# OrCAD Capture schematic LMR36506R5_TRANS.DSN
size D; title: LMR36506R5, 3 V 65 V, 0.6-A Ultra-Small Synchronous; rev: 1.0; note: Datasheet: SNVSBB6        EVM: SNVU671
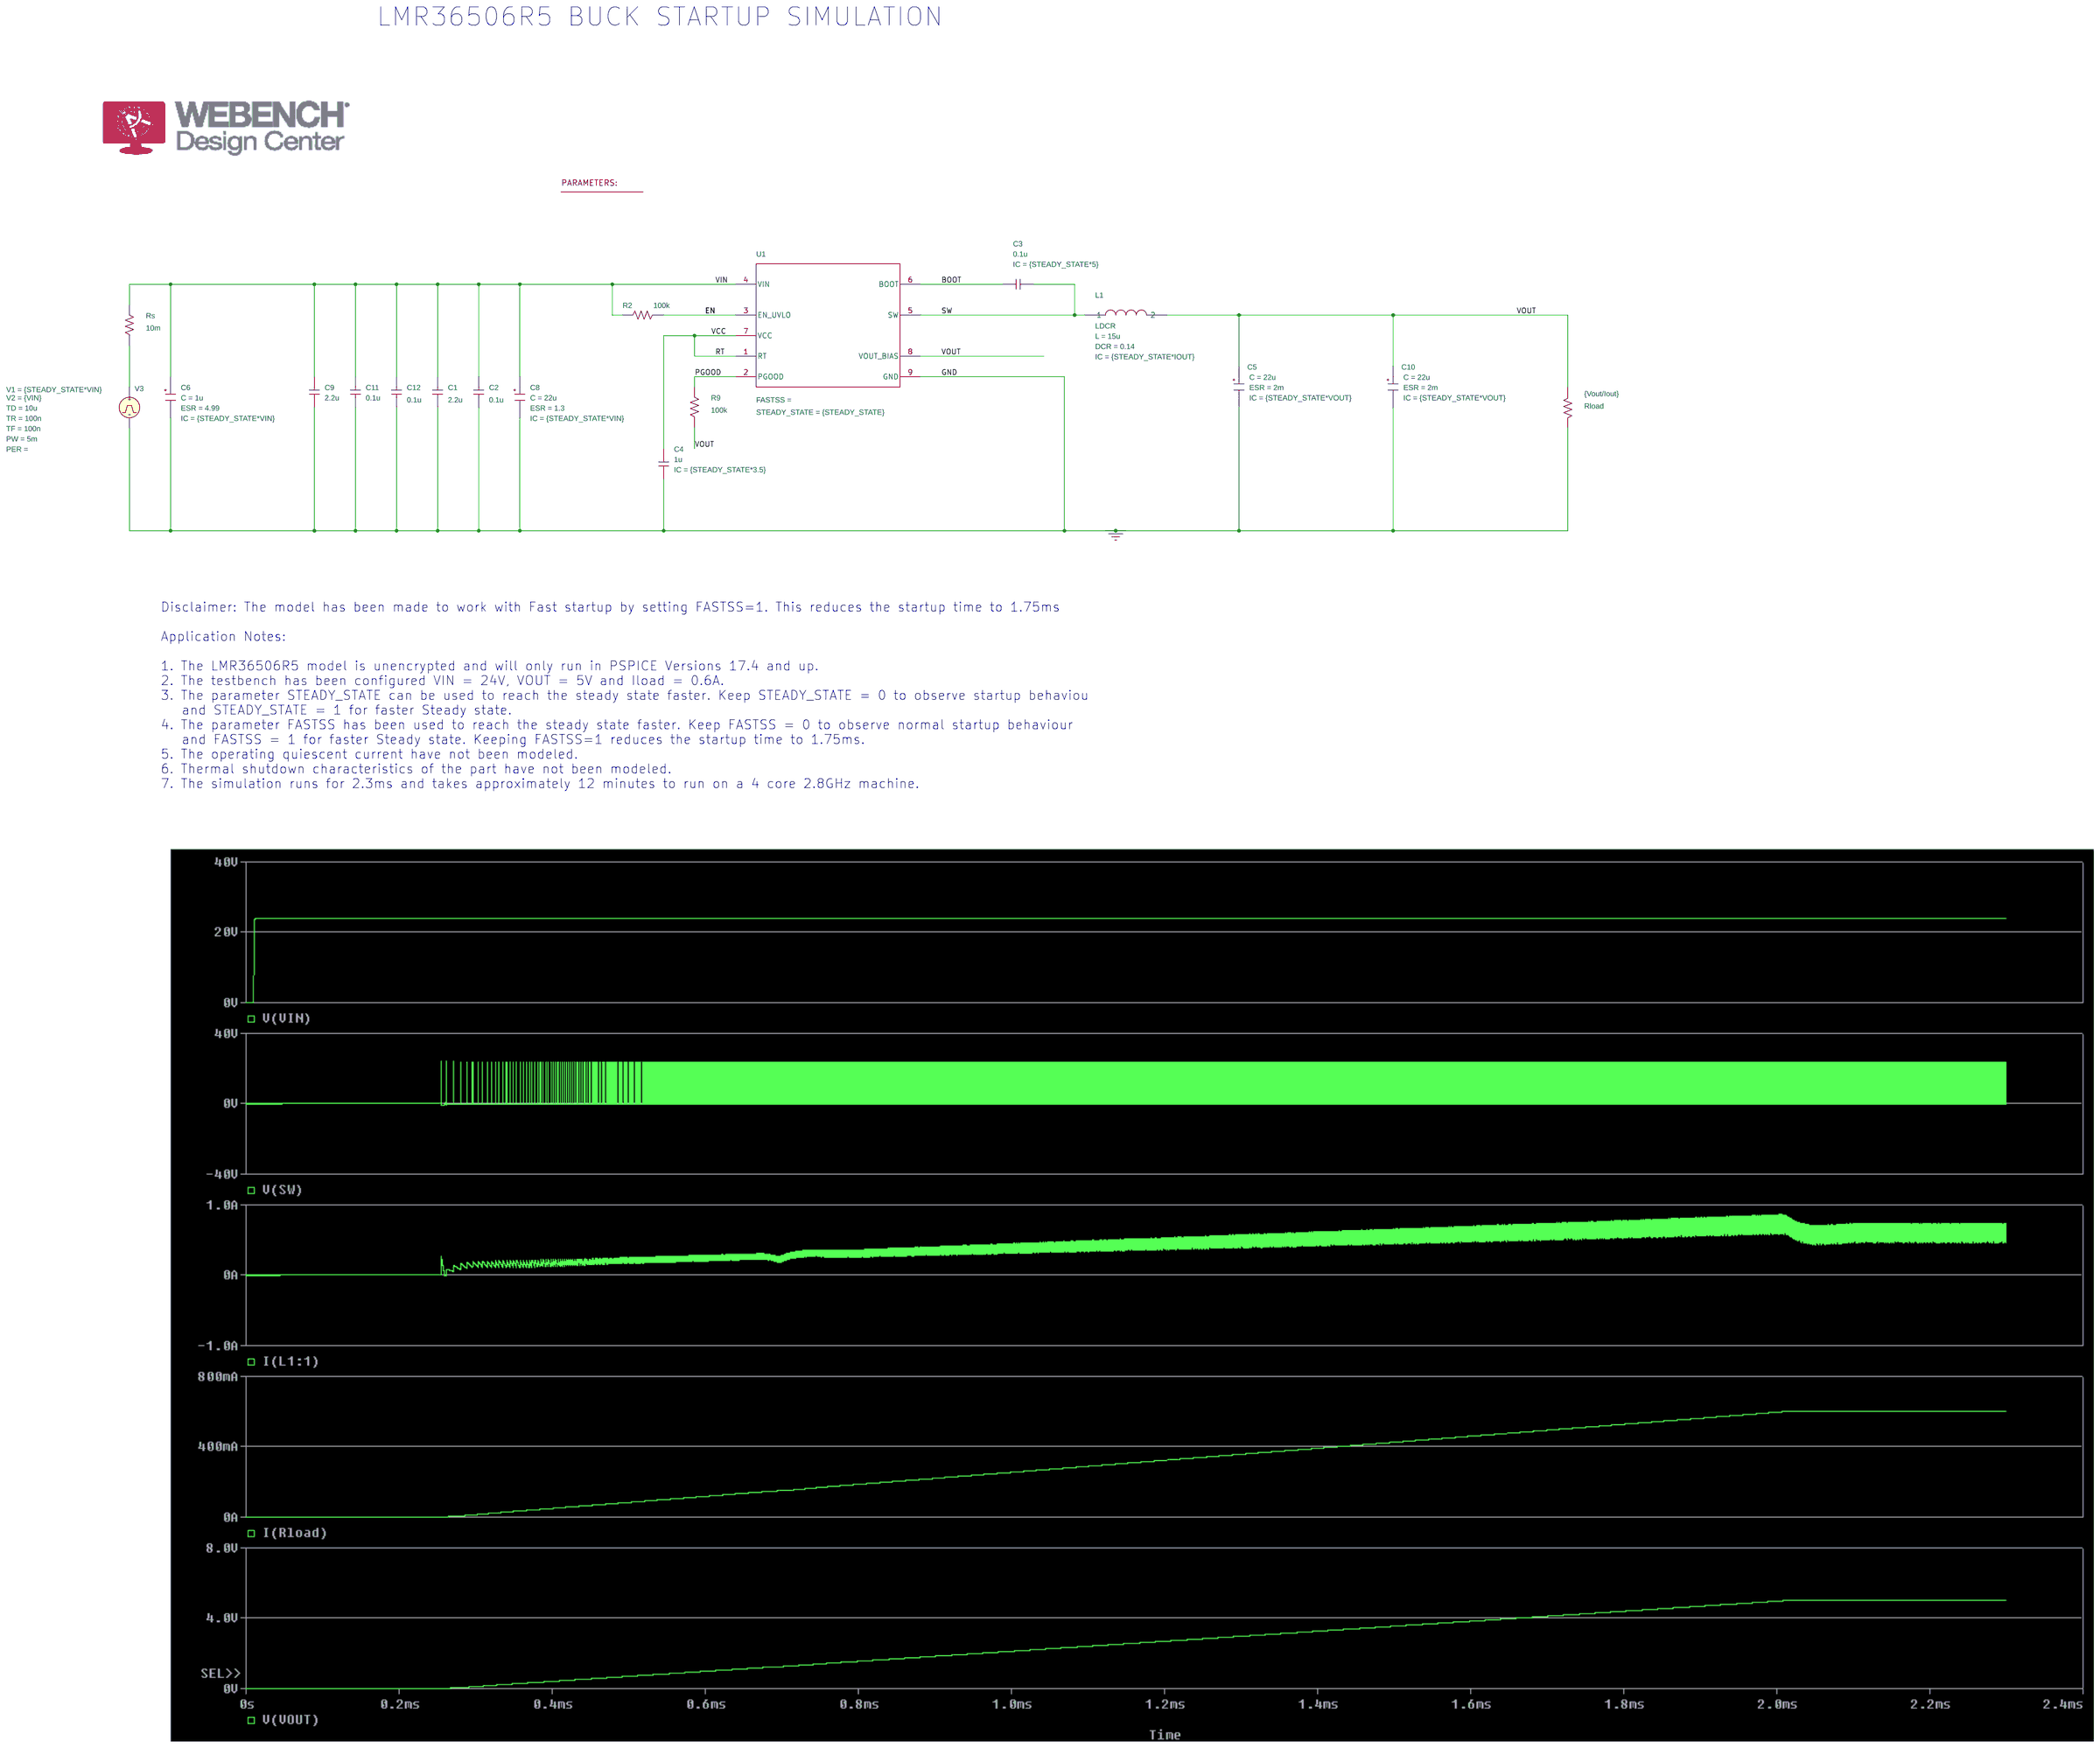
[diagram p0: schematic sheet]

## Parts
5  PARAM
C1  2.2u  [RAD/CK05]
C2  0.1u  [RAD/CK05]
C3  0.1u  [CK05]
C4  1u  [RAD/CK05]
C5  CESR
C6  CESR
C8  CESR
C9  2.2u  [RAD/CK05]
C10  CESR
C11  0.1u  [RAD/CK05]
C12  0.1u  [RAD/CK05]
L1  LDCR
R2  100k  [AX/RC05]
R9  100k  [RC05]
Rload  {Vout/Iout}  [AX/RC05]
Rs  10m  [AX/RC05]
U1  Value  [RPE0009A-MFG]
V3  VPULSE

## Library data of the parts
5 = PARAM: IOUT: 0.6; STEADY_STATE: 0; VIN: 24
C1 C2 C9 C11 C12 = C
C3 = C: IC: {STEADY_STATE*5}
C4 = C: IC: {STEADY_STATE*3.5}
C5 C10 = CESR_0: C: 22u; ESR: 2m; IC: {STEADY_STATE*VOUT}; PSpiceTemplate: X^@REFDES %IN %OUT @MODEL PARAMS:  ?C|C=@C||C=100u|  ?ESR|ESR=@ESR||ESR=0.01| ?X|X=@X||X=2|  ?IC|IC=@IC||IC=2|; X: 1
C6 = CESR_0: C: 1u; ESR: 4.99; IC: {STEADY_STATE*VIN}; PSpiceTemplate: X^@REFDES %IN %OUT @MODEL PARAMS:  ?C|C=@C||C=100u|  ?ESR|ESR=@ESR||ESR=0.01| ?X|X=@X||X=2|  ?IC|IC=@IC||IC=2|; X: 1
C8 = CESR_0: C: 22u; ESR: 1.3; IC: {STEADY_STATE*VIN}; PSpiceTemplate: X^@REFDES %IN %OUT @MODEL PARAMS:  ?C|C=@C||C=100u|  ?ESR|ESR=@ESR||ESR=0.01| ?X|X=@X||X=2|  ?IC|IC=@IC||IC=2|; X: 1
L1 = LDCR: DCR: 0.14; IC: {STEADY_STATE*IOUT}; L: 15u; PSpiceTemplate: X^@REFDES %1 %2 @MODEL PARAMS: ?L|L=@L||L=10U| ?DCR|DCR=@DCR||DCR=20M| ?IC|IC=@IC||IC=0|
R2 R9 Rload Rs = R
U1 = LMR36506R5RPE_TRANS: STEADY_STATE: {STEADY_STATE}
V3 = VPULSE: PW: 5m; TD: 10u; TF: 100n; TR: 100n; V1: {STEADY_STATE*VIN}; V2: {VIN}

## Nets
VIN: C1.2 C2.2 C6.1(IN) C8.1(IN) C9.2 C11.2 C12.2 R2.2 Rs.2 U1.4(VIN)
0: C1.1 C2.1 C4.2 C5.2(OUT) C6.2(OUT) C8.2(OUT) C9.1 C10.2(OUT) C11.1 C12.1 Rload.2 U1.9(GND) V3.2(-)
BOOT: C3.1 U1.6(BOOT)
EN: R2.1 U1.3(EN_UVLO)
PGOOD: R9.2 U1.2(PGOOD)
RT: C4.1 U1.1(RT) U1.7(VCC)
SW: C3.2 L1.1 U1.5(SW)
VOUT: C5.1(IN) C10.1(IN) L1.2 R9.1 Rload.1 U1.8(VOUT_BIAS)
N01178: Rs.1 V3.1(+)

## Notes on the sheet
- LMR36506R5 BUCK STARTUP SIMULATION
- Disclaimer: The model has been made to work with Fast startup by setting FASTSS=1. This reduces the startup time to 1.75ms
  Application Notes:
  1. The LMR36506R5 model is unencrypted and will only run in PSPICE Versions 17.4 and up.
  2. The testbench has been configured VIN = 24V, VOUT = 5V and Iload = 0.6A.
  3. The parameter STEADY_STATE can be used to reach the steady state faster. Keep STEADY_STATE = 0 to observe startup behaviou
     and STEADY_STATE = 1 for faster Steady state.
  4. The parameter FASTSS has been used to reach the steady state faster. Keep FASTSS = 0 to observe normal startup behaviour
     and FASTSS = 1 for faster Steady state. Keeping FASTSS=1 reduces the startup time to 1.75ms.
  5. The operating quiescent current have not been modeled.
  6. Thermal shutdown characteristics of the part have not been modeled.
  7. The simulation runs for 2.3ms and takes approximately 12 minutes to run on a 4 core 2.8GHz machine.
